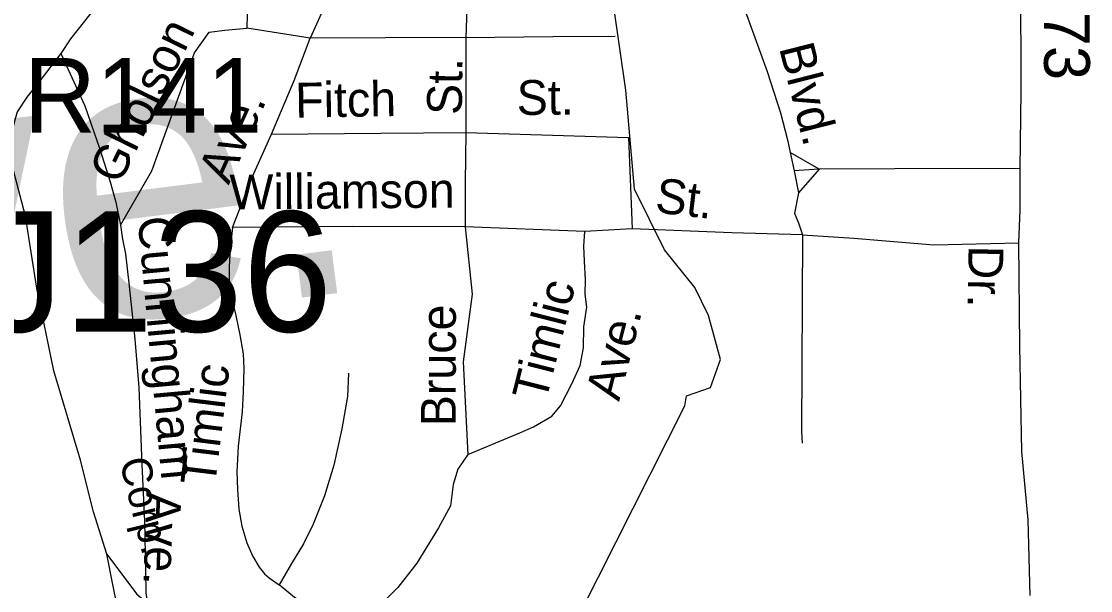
# Model space of a CAD drawing. Extents: x 1553981 to 1780076, y 812965 to 996873.
# Drawn here: x 1634040.5 to 1634404.9, y 847324.5 to 847518.6 of the extents above; entities that cross this region are included whole.
import ezdxf

# ---------------------------------------------------------------- set-up
doc = ezdxf.new("R2010")
doc.units = 0
for name, color, linetype in [('Exist Hydrographic Creek Single Shore', 7, 'Continuous'), ('Exist Railroad Mainline', 7, 'Continuous'), ('Exist Railroad Mainline Label', 7, 'Continuous'), ('Exist Railroad Siding', 7, 'Continuous'), ('Exist Road Non-System Structure Non-Sys Other Number Label', 7, 'Continuous'), ('Exist Road Non-System Type 51 Label', 7, 'Continuous'), ('Exist Road Primary US Structure RailRoad Number Label', 7, 'Continuous'), ('Exist Road Secondary Mileage Hundredths English Label', 7, 'Continuous'), ('Exist Road Secondary Type 51 Undivided 4 Lane Attributed', 7, 'Continuous'), ('Map Preparation Border Antique Large Shape', 7, 'Continuous'), ('Map Preparation Border County Name Lower Right Label', 7, 'Continuous')]:
    doc.layers.add(name, color=color, linetype=linetype)

msp = doc.modelspace()

# ---------------------------------------------------------------- linework, layer by layer
at = {"layer": 'Exist Hydrographic Creek Single Shore'}
msp.add_lwpolyline([(1634219.59, 847294.4), (1634266.67, 847387.47), (1634267.2, 847390.9), (1634275.38, 847393.8), (1634278.81, 847403.3), (1634274.72, 847418.34), (1634269.97, 847427.83), (1634259.68, 847440.76), (1634249.4, 847461.34), (1634246.49, 847495.1), (1634242.27, 847524.38)], dxfattribs=at)
at = {"layer": 'Exist Railroad Mainline'}
for points in [[(1634069.59, 847336.99), (1634065.04, 847351.37), (1634060.64, 847368.98), (1634051.46, 847399.41), (1634045.72, 847427.64), (1634041.88, 847452.15), (1634034.57, 847479.87), (1634029.42, 847500.24), (1634025.86, 847513.54), (1634017.81, 847533.26), (1634011.98, 847548.57), (1634003.31, 847566.4), (1633992.69, 847588.28), (1633986.83, 847606.17), (1633984.64, 847618.48), (1633983.29, 847629.76), (1633984.15, 847641.13), (1633985.54, 847652.88), (1633986.19, 847663.47), (1633989.36, 847672.75), (1633996.01, 847690.35), (1634006.19, 847708.12), (1634011.33, 847719.83)], [(1634073.7, 847316.25), (1634069.59, 847336.99)]]:
    msp.add_lwpolyline(points, dxfattribs=at)
at = {"layer": 'Exist Railroad Siding'}
msp.add_lwpolyline([(1634069.59, 847336.99), (1634079.73, 847323.44), (1634089.37, 847315.13)], dxfattribs=at)
at = {"layer": 'Exist Road Secondary Type 51 Undivided 4 Lane Attributed'}
msp.add_lwpolyline([(1634384.32, 847322.86), (1634383.63, 847348.63), (1634381.54, 847371.95), (1634380.84, 847407.81), (1634380.52, 847443.06), (1634380.93, 847454.19), (1634380.89, 847468.45), (1634381.3, 847494.71), (1634381.14, 847533.45), (1634381.94, 847573.3), (1634381.84, 847594.92), (1634382.59, 847626.93), (1634382.79, 847640.43), (1634382.28, 847656.17), (1634383.08, 847667.62), (1634382.16, 847682.68), (1634380.31, 847693.34), (1634377.76, 847702.6), (1634375.44, 847708.86), (1634371.85, 847716.12), (1634365.84, 847729.29), (1634359.55, 847740.73), (1634354.11, 847749.21), (1634352.86, 847751.35)], dxfattribs=at)
at = {"layer": 'Map Preparation Border County Name Lower Right Label'}
for p, q in [((1634138.94, 847512.89), (1634117.32, 847516.26)), ((1634302.51, 847473.89), (1634303.94, 847467.64)), ((1634312.43, 847468.24), (1634302.51, 847473.89)), ((1634312.43, 847468.24), (1634303.94, 847467.64)), ((1634312.43, 847468.24), (1634305.31, 847460.11)), ((1634303.94, 847467.64), (1634305.31, 847460.11)), ((1634232.53, 847447.01), (1634191.68, 847448.6)), ((1634248.62, 847447.89), (1634232.53, 847447.01))]:
    msp.add_line(p, q, dxfattribs=at)
for points in [[(1634082.36, 847544.96), (1634075.68, 847536.21), (1634063.72, 847520.79), (1634057.22, 847512.66), (1634053.91, 847507.68)], [(1634193.19, 847545.44), (1634192.53, 847529.69), (1634192.01, 847513.05)], [(1634117.98, 847543.65), (1634117.32, 847516.26)], [(1634152.17, 847544.69), (1634145.94, 847528.53), (1634138.94, 847512.89)], [(1634280.56, 847540.98), (1634286.78, 847523.39), (1634294.69, 847501.52), (1634299.24, 847487.44), (1634301.6, 847478.17), (1634302.51, 847473.89)], [(1634074.24, 847449.12), (1634084.87, 847467.66), (1634099.44, 847507.87), (1634104.52, 847514.93), (1634109.81, 847515.6), (1634117.32, 847516.26)], [(1634125.69, 847480.09), (1634133.47, 847498.46), (1634138.94, 847512.89)], [(1634192.01, 847513.05), (1634164.43, 847512.99), (1634138.94, 847512.89)], [(1634192.01, 847513.05), (1634221.67, 847513.38), (1634242.91, 847513.55)], [(1634192.01, 847513.05), (1634192.01, 847496.94), (1634192.01, 847480.68)], [(1634053.91, 847507.68), (1634046.71, 847498.27), (1634042.29, 847492.73), (1634038.97, 847487.75), (1634037.31, 847481.66), (1634032.68, 847469.49), (1634029.15, 847461.56), (1634028.19, 847454.73), (1634027.78, 847448.27), (1634027.61, 847445.27)], [(1634053.91, 847507.68), (1634062.13, 847489.81), (1634067.16, 847474.97), (1634070.74, 847463.92), (1634072.62, 847456.9), (1634074.24, 847449.12), (1634074.92, 847444.37), (1634075.89, 847439.33)], [(1634112.47, 847448.29), (1634119.22, 847465.69), (1634125.69, 847480.09)], [(1634125.69, 847480.09), (1634162.95, 847480.53), (1634192.01, 847480.68)], [(1634192.01, 847480.68), (1634191.68, 847463.64), (1634191.68, 847448.6)], [(1634192.01, 847480.68), (1634247.38, 847479.04), (1634248.62, 847447.89)], [(1634380.89, 847468.45), (1634338.17, 847468.34), (1634312.43, 847468.24)], [(1634305.31, 847460.11), (1634304.01, 847453.15), (1634305.44, 847449.55), (1634306.69, 847445.8)], [(1634112.47, 847448.29), (1634111.62, 847441.05), (1634111.27, 847435.06), (1634111.34, 847429.73), (1634111.88, 847425.31), (1634113.51, 847418.28), (1634114.9, 847411.77), (1634116.07, 847405.24), (1634116.24, 847400.24), (1634116.11, 847392.34), (1634115.77, 847385.49), (1634114.33, 847373.76), (1634113.95, 847365.01), (1634114.11, 847359.03), (1634114.62, 847352.32), (1634115.65, 847346.5), (1634117.34, 847340.81), (1634119.25, 847336.44), (1634121.55, 847332.54), (1634123.35, 847330.31), (1634124.9, 847328.85), (1634128.35, 847326.55)], [(1634191.68, 847448.6), (1634153.2, 847448.66), (1634124.23, 847448.38), (1634112.47, 847448.29)], [(1634191.68, 847448.6), (1634194.07, 847425.55), (1634191.08, 847402.51), (1634192.67, 847370.98)], [(1634192.67, 847370.98), (1634210.35, 847378.31), (1634215.05, 847380.33), (1634221.33, 847383.96), (1634224.28, 847387.56), (1634228.11, 847395.04), (1634230.96, 847401.26), (1634232.12, 847407.33), (1634232.14, 847414.47), (1634233.26, 847421.2), (1634232.65, 847425.59), (1634232.76, 847430.47), (1634232.44, 847436.84), (1634232.22, 847441.99), (1634232.53, 847447.01)], [(1634306.69, 847445.8), (1634282.62, 847446.46), (1634248.62, 847447.89)], [(1634306.69, 847445.8), (1634306.43, 847378.75), (1634306.65, 847374.77)], [(1634306.69, 847445.8), (1634324.17, 847444.66), (1634351.52, 847442.41), (1634380.52, 847443.06)], [(1634075.89, 847439.33), (1634077.19, 847428.35), (1634079.15, 847410.3), (1634080.52, 847393.78), (1634081.51, 847367.52), (1634082.45, 847348.25), (1634082.71, 847331.51), (1634082.82, 847323.75), (1634083.72, 847318.65), (1634085.41, 847313.22), (1634086.75, 847310.14), (1634089.07, 847306.41), (1634091.29, 847304.62), (1634094.5, 847302.58), (1634100.7, 847300.22), (1634112.89, 847295.55), (1634129.78, 847289.78), (1634144.95, 847284.32)], [(1634151.96, 847398.69), (1634151.57, 847390.69), (1634149.64, 847379.72), (1634146.97, 847367.27), (1634143.8, 847356.83), (1634139.9, 847347.13), (1634136.57, 847340.44), (1634132.48, 847333.8), (1634128.35, 847326.55)], [(1634192.67, 847370.98), (1634189.28, 847365.89), (1634187.69, 847360.69), (1634186.73, 847353.41), (1634182.63, 847345.98), (1634175.2, 847333.85), (1634168.78, 847325.58), (1634161.45, 847318.05), (1634157.42, 847315.36), (1634153.4, 847314.44), (1634150.4, 847314.72), (1634145.42, 847315.8), (1634140.46, 847317.88), (1634133.54, 847322.22), (1634128.35, 847326.55)]]:
    msp.add_lwpolyline(points, dxfattribs=at)

# ---------------------------------------------------------------- texts
at = {"layer": 'Exist Railroad Mainline Label'}
msp.add_text('Corp.', height=10.253, rotation=283.9005, dxfattribs=at).set_placement((1634073.82, 847368.7))
at = {"layer": 'Exist Road Non-System Structure Non-Sys Other Number Label'}
msp.add_text('J136', height=41.01, dxfattribs=at).set_placement((1634027.48, 847412.81))
at = {"layer": 'Exist Road Non-System Type 51 Label'}
for s, height, rotation, p in [('Gholson', 11.875, 63.8898, (1634073.85, 847462.52)), ('Blvd.', 11.875, 284.2862, (1634298.68, 847509.61)), ('St.', 11.875, 89.1045, (1634190.55, 847486.62)), ('Fitch', 11.875, 0.8979, (1634133.87, 847485.76)), ('St.', 11.875, 0.4089, (1634209.35, 847486.67)), ('Ave.', 95, 7.1831, (1633907.41, 847395.59)), ('Ave.', 11.875, 65.8051, (1634111.11, 847462.64)), ('Williamson', 11.875, 0.5282, (1634111.45, 847454.43)), ('St.', 11.875, 353.2101, (1634256.2, 847453.53)), ('Cunningham', 11.875, 275.2052, (1634080.08, 847451.66)), ('Timlic', 11.875, 75.6935, (1634219.17, 847388.48)), ('Bruce', 11.875, 89.9432, (1634188.52, 847380.56)), ('Ave.', 11.875, 75.6935, (1634244.2, 847388.81)), ('Timlic', 11.875, 83.0042, (1634106.44, 847359.94)), ('Ave.', 11.875, 268.1769, (1634083.1, 847358.32))]:
    msp.add_text(s, height=height, rotation=rotation, dxfattribs=at).set_placement(p)
at = {"layer": 'Exist Road Primary US Structure RailRoad Number Label'}
msp.add_text('R141', height=25.426, dxfattribs=at).set_placement((1634041.31, 847480.66))
at = {"layer": 'Exist Road Secondary Mileage Hundredths English Label'}
msp.add_text('1.73', height=15.625, rotation=270.2413, dxfattribs=at).set_placement((1634388.93, 847539.23))
at = {"layer": 'Map Preparation Border Antique Large Shape'}
msp.add_text('Dr.', height=11.875, rotation=268.9786, dxfattribs=at).set_placement((1634363.36, 847442.24))

doc.saveas('drawing.dxf')
